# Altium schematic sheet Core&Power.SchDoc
size A3
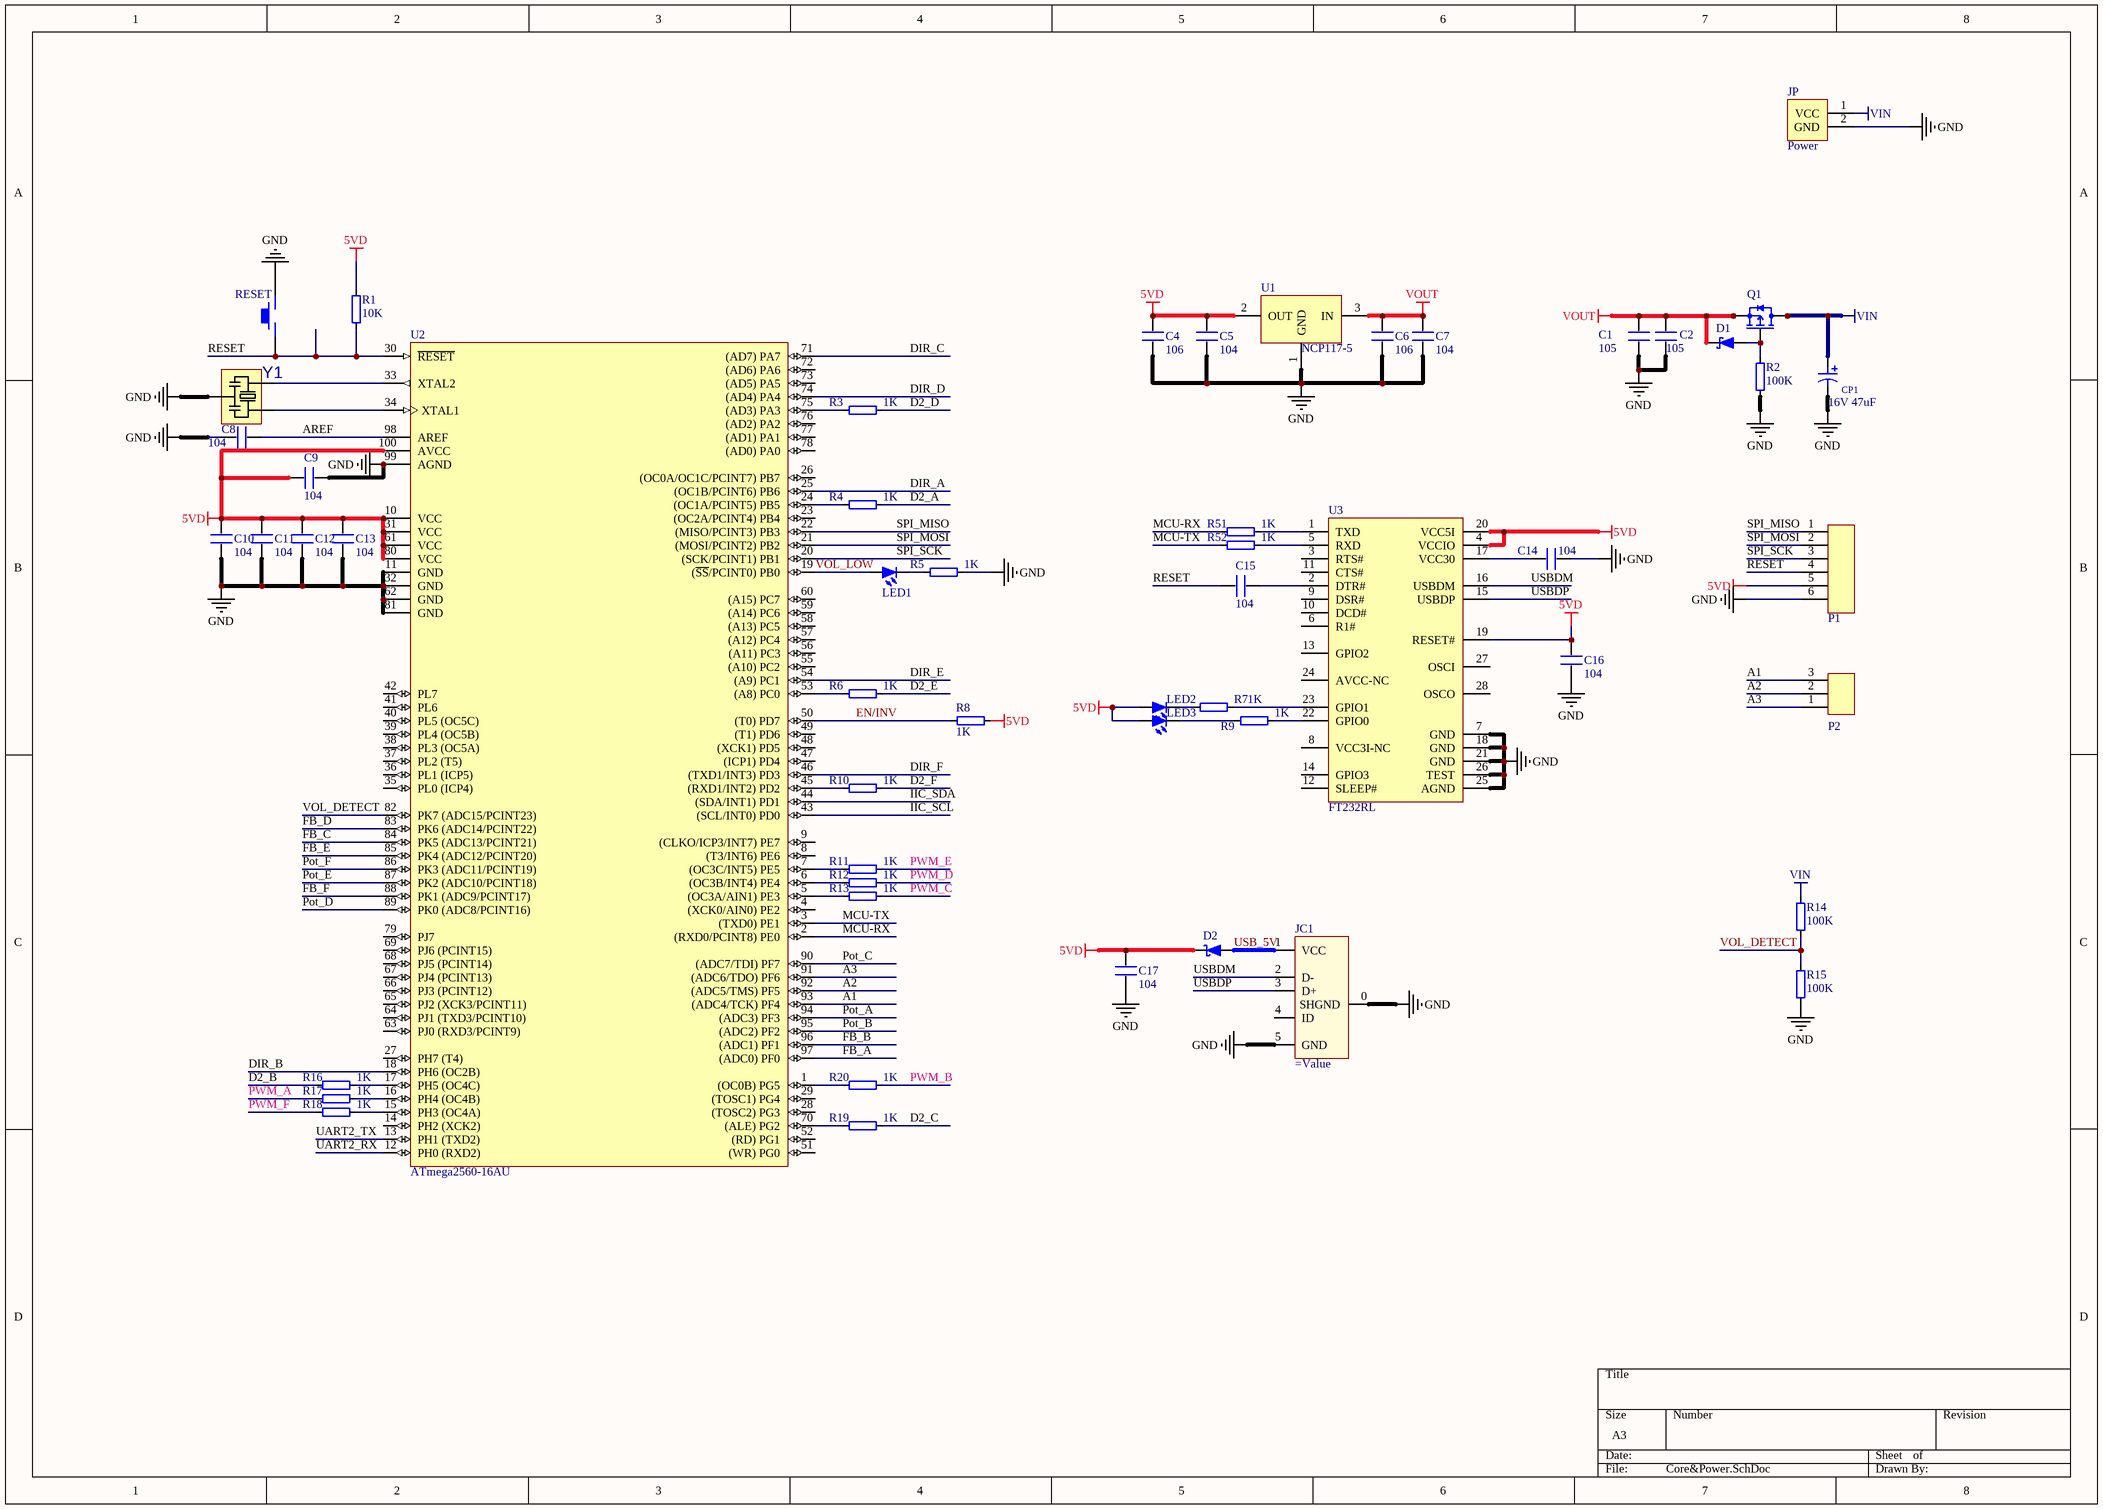
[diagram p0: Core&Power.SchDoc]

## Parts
C1  105  [SM0603C]
C2  105  [SM0603C]
C4  106  [SM0603C]
C5  104  [SM0603C]
C6  106  [SM0603C]
C7  104  [SM0603C]
C8  104  [SM0603C]
C9  104  [SM0603C]
C10  104  [SM0603C]
C11  104  [SM0603C]
C12  104  [SM0603C]
C13  104  [SM0603C]
C14  104  [SM0603C]
C15  104  [SM0603C]
C16  104  [SM0603C]
C17  104  [SM0603C]
CP1  16V 47uF  [SMD5-Al]
D1  B5819W  [SOD-323]  (value not drawn)
D2  B5819W  [SOD-323]  (value not drawn)
JC1  (no value)  [MICRO-USB2]
JP  Power  [AM1015-M]
LED1  Blue LED  [SM0805LED]  (value not drawn)
LED2  Blue LED  [SM0805LED]  (value not drawn)
LED3  Blue LED  [SM0805LED]  (value not drawn)
P1  JC6  [HDR1X6]  (value not drawn)
P2  JC3  [HDR1X3]  (value not drawn)
Q1  (no value)
R1  10K  [SM0603R]
R2  100K  [SM0603R]
R3  1K  [SM0603R]
R4  1K  [SM0603R]
R5  1K  [SM0603R]
R6  1K  [SM0603R]
R7  1K  [SM0603R]
R8  1K  [SM0603R]
R9  1K  [SM0603R]
R10  1K  [SM0603R]
R11  1K  [SM0603R]
R12  1K  [SM0603R]
R13  1K  [SM0603R]
R14  100K  [SM0603R]
R15  100K  [SM0603R]
R16  1K  [SM0603R]
R17  1K  [SM0603R]
R18  1K  [SM0603R]
R19  1K  [SM0603R]
R20  1K  [SM0603R]
R51  1K  [SM0603R]
R52  1K  [SM0603R]
RESET  KEY_M  [SPNO_SMD]  (value not drawn)
U1  NCP117-5  [SOT223-4]
U2  ATmega2560-16AU  [100A_N]
U3  FT232RL  [SSOP-28]
Y1  CSTCE16M0V53-R0  [OSC_CSTCE16M0V53-R0]  (value not drawn)

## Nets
5VD: C4.2 C5.2 C9.2 C10.1 C11.1 C12.1 C13.1 C16.2 C17.2 D2.1(C) LED2.2(A) LED3.2(A) P1.5 R1.2 R8.1 U1.2(OUT) U2.10(VCC) U2.31(VCC) U2.61(VCC) U2.80(VCC) U2.100(AVCC) U3.4(VCCIO) U3.19(RESET#) U3.20(VCC5I)
GND: C1.1 C2.1 C4.1 C5.1 C6.1 C7.1 C8.1 C9.1 C10.2 C11.2 C12.2 C13.2 C14.2 C16.1 C17.1 CP1.2 JC1.0(SHGND) JC1.5(GND) JP.2(GND) P1.6 R2.1 R5.2 R15.1 RESET.1 U1.1(GND) U2.11(GND) U2.32(GND) U2.62(GND) U2.81(GND) U2.99(AGND) U3.7(GND) U3.18(GND) U3.21(GND) U3.25(AGND) U3.26(TEST) Y1.2
VIN: CP1.1 JP.1(VCC) Q1.5(D) Q1.6(D) Q1.7(D) Q1.8(D) R14.2
VOUT: C1.2 C2.2 C6.2 C7.2 D1.1(C) Q1.1(S) Q1.2(S) Q1.3(S) U1.3(IN)
A1: P2.3 U2.93((ADC4/TCK)_PF4)
A2: P2.2 U2.92((ADC5/TMS)_PF5)
A3: P2.1 U2.91((ADC6/TDO)_PF6)
AREF: C8.2 U2.98(AREF)
D2_A: R4.2
D2_B: R16.2
D2_C: R19.2
D2_D: R3.2
D2_E: R6.2
D2_F: R10.2
DIR_A: U2.25((OC1B/PCINT6)_PB6)
DIR_B: U2.18(PH6_(OC2B))
DIR_C: U2.71((AD7)_PA7)
DIR_D: U2.74((AD4)_PA4)
DIR_E: U2.54((A9)_PC1)
DIR_F: U2.46((TXD1/INT3)_PD3)
EN/INV: R8.2 U2.50((T0)_PD7)
FB_A: U2.97((ADC0)_PF0)
FB_B: U2.96((ADC1)_PF1)
FB_C: U2.84(PK5_(ADC13/PCINT21))
FB_D: U2.83(PK6_(ADC14/PCINT22))
FB_E: U2.85(PK4_(ADC12/PCINT20))
FB_F: U2.88(PK1_(ADC9/PCINT17))
IIC_SCL: U2.43((SCL/INT0)_PD0)
IIC_SDA: U2.44((SDA/INT1)_PD1)
MCU-RX: R51.1 U2.2((RXD0/PCINT8)_PE0)
MCU-TX: R52.1 U2.3((TXD0)_PE1)
Pot_A: U2.94((ADC3)_PF3)
Pot_B: U2.95((ADC2)_PF2)
Pot_C: U2.90((ADC7/TDI)_PF7)
Pot_D: U2.89(PK0_(ADC8/PCINT16))
Pot_E: U2.87(PK2_(ADC10/PCINT18))
Pot_F: U2.86(PK3_(ADC11/PCINT19))
PWM_A: R17.1
PWM_B: R20.2
PWM_C: R13.2
PWM_D: R12.2
PWM_E: R11.2
PWM_F: R18.1
RESET: C15.2 P1.4 R1.1 RESET.2 U2.30(~{RESET})
SPI_MISO: P1.1 U2.22((MISO/PCINT3)_PB3)
SPI_MOSI: P1.2 U2.21((MOSI/PCINT2)_PB2)
SPI_SCK: P1.3 U2.20((SCK/PCINT1)_PB1)
UART2_RX: U2.12(PH0_(RXD2))
UART2_TX: U2.13(PH1_(TXD2))
USB_5V: D2.2(A) JC1.1(VCC)
USBDM: JC1.2(D-) U3.16(USBDM)
USBDP: JC1.3(D+) U3.15(USBDP)
VOL_DETECT: R14.1 R15.2 U2.82(PK7_(ADC15/PCINT23))
VOL_LOW: LED1.2(A) U2.19((~{SS}/PCINT0)_PB0)
NetC14_1: C14.1 U3.17(VCC30)
NetC15_1: C15.1 U3.2(DTR#)
NetD1_2: D1.2(A) Q1.4(G) R2.2
NetLED1_1: LED1.1(C) R5.1
NetLED2_1: LED2.1(C) R7.1
NetLED3_1: LED3.1(C) R9.1
NetR3_1: R3.1 U2.75((AD3)_PA3)
NetR4_1: R4.1 U2.24((OC1A/PCINT5)_PB5)
NetR6_1: R6.1 U2.53((A8)_PC0)
NetR7_2: R7.2 U3.23(GPIO1)
NetR9_2: R9.2 U3.22(GPIO0)
NetR10_1: R10.1 U2.45((RXD1/INT2)_PD2)
NetR11_1: R11.1 U2.7((OC3C/INT5)_PE5)
NetR12_1: R12.1 U2.6((OC3B/INT4)_PE4)
NetR13_1: R13.1 U2.5((OC3A/AIN1)_PE3)
NetR16_1: R16.1 U2.17(PH5_(OC4C))
NetR17_2: R17.2 U2.16(PH4_(OC4B))
NetR18_2: R18.2 U2.15(PH3_(OC4A))
NetR19_1: R19.1 U2.70((ALE)_PG2)
NetR20_1: R20.1 U2.1((OC0B)_PG5)
NetR51_2: R51.2 U3.1(TXD)
NetR52_2: R52.2 U3.5(RXD)
NetU2_33: U2.33(XTAL2) Y1.3
NetU2_34: U2.34(XTAL1) Y1.1

Not connected (* = marked no-connect by the designer): JC1 4(ID); U2 4((XCK0/AIN0)_PE2) 8((T3/INT6)_PE6) 9((CLKO/ICP3/INT7)_PE7) 14(PH2_(XCK2)) 23((OC2A/PCINT4)_PB4) 26((OC0A/OC1C/PCINT7)_PB7) 27(PH7_(T4)) 28((TOSC2)_PG3) 29((TOSC1)_PG4) 35(PL0_(ICP4)) 36(PL1_(ICP5)) 37(PL2_(T5)) 38(PL3_(OC5A)) 39(PL4_(OC5B)) 40(PL5_(OC5C)) 41(PL6) 42(PL7) 47((ICP1)_PD4) 48((XCK1)_PD5) 49((T1)_PD6) 51((WR)_PG0) 52((RD)_PG1) 55((A10)_PC2) 56((A11)_PC3) 57((A12)_PC4) 58((A13)_PC5) 59((A14)_PC6) 60((A15)_PC7) 63(PJ0_(RXD3/PCINT9)) 64(PJ1_(TXD3/PCINT10)) 65(PJ2_(XCK3/PCINT11)) 66(PJ3_(PCINT12)) 67(PJ4_(PCINT13)) 68(PJ5_(PCINT14)) 69(PJ6_(PCINT15)) 72((AD6)_PA6) 73((AD5)_PA5) 76((AD2)_PA2) 77((AD1)_PA1) 78((AD0)_PA0) 79(PJ7); U3 3(RTS#) 6(R1#) 8(VCC3I-NC) 9(DSR#) 10(DCD#) 11(CTS#) 12(SLEEP#) 13(GPIO2) 14(GPIO3) 24(AVCC-NC) 27(OSCI) 28(OSCO)

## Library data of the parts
C1 C2 C4-C17 = C
CP1 = 2.1.2.50.5162200: Cap, 22uF, 20%, 16V; Manufactory: ALUMINUM; InstallMode: SMD
D1 D2 = 2.1.4.21.0058190: Dio, Schottky, B5819W, 1A, 40V, SOD123, SSC; Manufactory: Silicon Standard Corp.; InstallMode: SMD
JC1 = 2.1.7.20.6780302: Mini USB Jack, SD-67803-002, Molex
LED1-LED3 = 2.1.4.10.0060330: LED, Blue, 5mA, 0603; Manufactory: Everlight Electronics Co., Ltd.; Name: Blue LED[0603]; InstallMode: SMD
Q1 = IRF7842: Mos/P; InstallMode: SMD
R1-R20 R51 R52 = RES
U2 = ATmega2560-16AU: 8-bit AVR Microcontroller, 4.5-5.5V, 256KB Flash, 4KB EEPROM, 8KB SRAM, 86 GPIO pins, 100-pin TQFP, Industrial Grade (-40癈 to 85癈), Pb-Free
Y1 = CSTCE16M0V53-R0: Ceramic Resonator 16MHz ??0.5% (Tol) ??0.3% (Stability) 15pF 40Ohm 3-Pin CSMD T/R; MF: Murata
